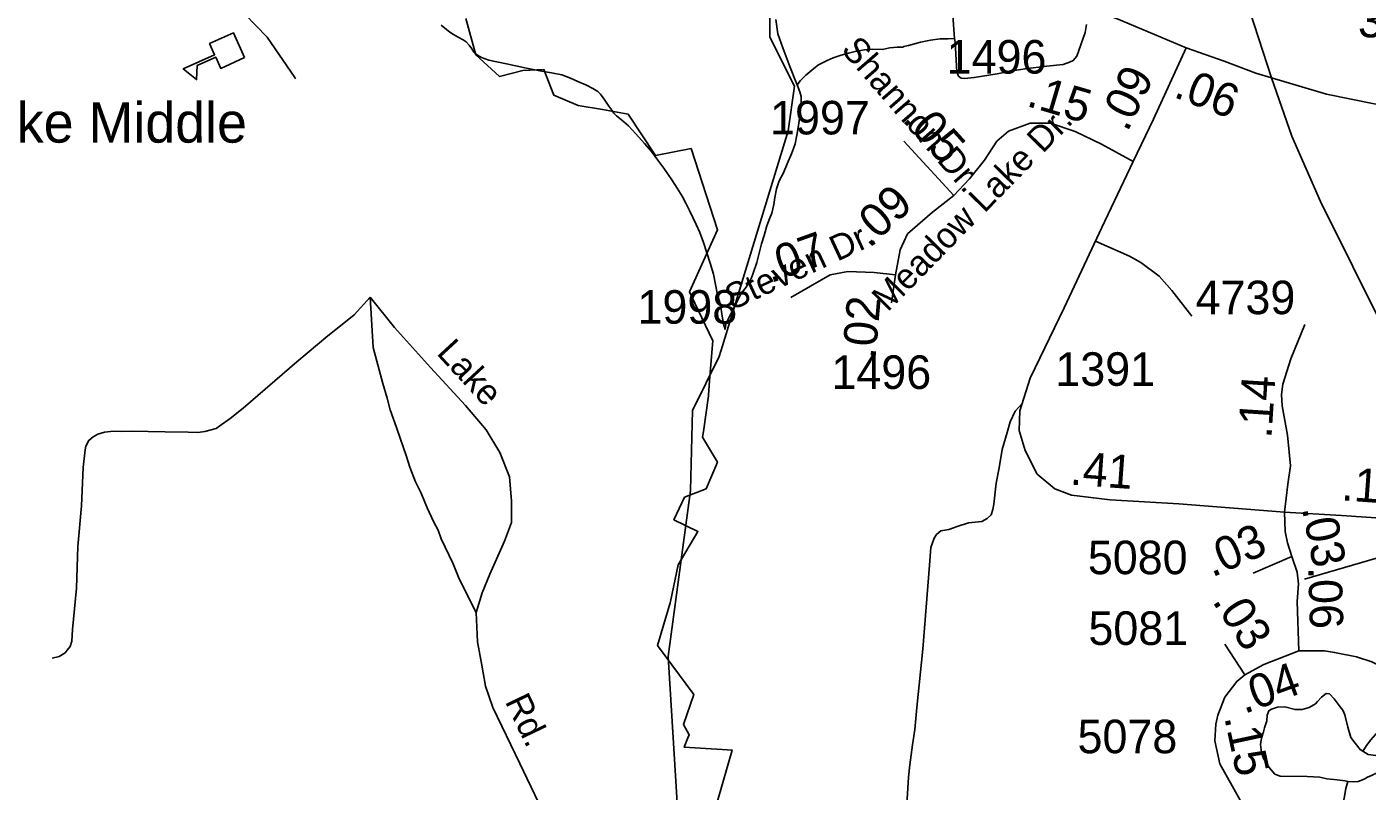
# Model space of a CAD drawing. Extents: x 2001466 to 2224147, y 644118 to 847247.
# Drawn here: x 2071075 to 2076073, y 692488 to 695337 of the extents above; entities that cross this region are included whole.
import ezdxf

# ---------------------------------------------------------------- set-up
doc = ezdxf.new("R2010")
doc.units = 0
for name, color, linetype in [('Exist Boundary Political City Limit New', 7, 'Continuous'), ('Exist Cultural Educational Facility Elementary CELL', 7, 'Continuous'), ('Exist Cultural Educational Facility High Label', 7, 'Continuous'), ('Exist Hydrographic Misc Water Feature', 7, 'Continuous'), ('Exist Road Non-System Type 51', 7, 'Continuous'), ('Exist Road Non-System Type 51 Label', 7, 'Continuous'), ('Exist Road Secondary Mileage Hundredths English Label', 7, 'Continuous'), ('Exist Road Secondary Type 51 Attributed', 7, 'Continuous'), ('Exist Road Secondary Type 51 Label', 7, 'Continuous'), ('Exist Road Secondary Type 51 Number Label', 7, 'Continuous'), ('Map Preparation Boundary City Limit Buffer Line', 7, 'Continuous')]:
    doc.layers.add(name, color=color, linetype=linetype)

msp = doc.modelspace()

# ---------------------------------------------------------------- linework, layer by layer
at = {"layer": 'Exist Boundary Political City Limit New'}
for points in [[(2073597.8, 693827.8), (2073616.8, 693960.9), (2073617.1, 693965.4), (2073622.4, 694032.9), (2073632.4, 694166.4), (2073605.2, 694223.8), (2073566.1, 694306.5), (2073546.2, 694348.6), (2073650.9, 694580.4), (2073552, 694882.9), (2073419.4, 694856.8), (2073317.4, 695010.8), (2073221.4, 695028.8), (2073131.1, 695042.9), (2073039.5, 695082.1), (2073002.2, 695177.9), (2072924.5, 695174.2), (2072837.9, 695151.9), (2072749.4, 695232.5), (2072712, 695367.1)], [(2073648.6, 692446.9), (2073704.6, 692641.3), (2073667.4, 692643.6), (2073525.8, 692652.3), (2073540.2, 692686.5), (2073545, 692697.8), (2073523.2, 692736.1), (2073562.1, 692847.8), (2073426.8, 693031.2), (2073473.8, 693189.9), (2073474.9, 693194.9), (2073503.8, 693331.6), (2073577.6, 693455.6), (2073487.8, 693499.7), (2073527.6, 693583.3), (2073608.1, 693614.9), (2073650.2, 693714.5), (2073594.9, 693807.1), (2073597.8, 693827.8)]]:
    msp.add_lwpolyline(points, dxfattribs=at)
at = {"layer": 'Exist Cultural Educational Facility Elementary CELL'}
msp.add_lwpolyline([(2071887.1, 695221.9), (2071797.9, 695181.6), (2071779, 695223.6), (2071710.5, 695192.8), (2071707.7, 695139.9), (2071657.8, 695179.6), (2071775, 695232.4), (2071756.1, 695274.3), (2071845.4, 695314.6)], close=True, dxfattribs=at)
at = {"layer": 'Exist Hydrographic Misc Water Feature'}
for points in [[(2073669.2, 694148), (2073914, 694948.9), (2073938, 695115.7), (2073845.9, 695298), (2073845.9, 695498.2), (2073986, 696249.9), (2073986, 696446.8), (2074069, 696799.4), (2074033.9, 697282.4), (2073942.1, 697556.6), (2074016.1, 698122.6), (2074223, 698630.2), (2074223, 698899.3), (2074256, 698941.2)], [(2074534.7, 695293.3), (2074524.6, 695431.1)], [(2072619.7, 695342.2), (2072639.6, 695326.2), (2072651.9, 695316.2), (2072665.8, 695308), (2072683.7, 695298.4), (2072701.7, 695288.3), (2072713.4, 695280.1), (2072723.9, 695268.4), (2072733.7, 695254.3), (2072741.5, 695242.2), (2072746, 695238.3), (2072755.7, 695230.3), (2072769.8, 695222.5), (2072797.9, 695212.5), (2072863.9, 695198.5), (2072937.7, 695182.8), (2072988, 695172.8), (2073031.7, 695164.9), (2073070, 695157.1), (2073102, 695145), (2073129.7, 695133), (2073161.9, 695119.2), (2073185.7, 695107.1), (2073203.7, 695095), (2073213.9, 695085.4), (2073224, 695071.3), (2073232.2, 695059.1), (2073245.7, 695041.2), (2073255.8, 695025.5), (2073264, 695015.3), (2073274.2, 695005.3), (2073291.9, 694989.6), (2073317.9, 694967.4), (2073346.2, 694937.6), (2073378, 694901.5), (2073404, 694871.6), (2073428.4, 694839.5), (2073450.4, 694809.9), (2073466.2, 694785.9), (2073480.3, 694765.9), (2073500.4, 694735.7), (2073518.9, 694705.8)], [(2073867.4, 695364.4), (2073875.4, 695310.4), (2073893.5, 695258.6), (2073919.7, 695188.5), (2073943.7, 695128.5), (2073947.8, 695120.6)], [(2075026.6, 695344.8), (2075020.9, 695314.9), (2074990.7, 695226.6), (2074977, 695210.4), (2074962.8, 695204.4), (2074939.1, 695196.3), (2074879, 695190.4), (2074797.4, 695180), (2074749.2, 695171.9), (2074693, 695161.8), (2074607.5, 695147.6), (2074571, 695143.4), (2074559.3, 695145.1), (2074549.2, 695153.2), (2074543.3, 695169.1), (2074537.1, 695279.1), (2074534.7, 695293.3)], [(2074534.7, 695293.3), (2074511.1, 695291.2), (2074481, 695291.3), (2074444.9, 695287), (2074406.9, 695279), (2074362.9, 695266.6), (2074345.2, 695262.8), (2074341.1, 695260.6)], [(2074341.1, 695260.6), (2074321, 695260.7), (2074293.1, 695258.5), (2074264.8, 695252.6), (2074229.2, 695252.8), (2074199.2, 695250.8), (2074163.3, 695244.9), (2074139.3, 695238.8), (2074111.3, 695230.9), (2074081.5, 695220.8), (2074059.4, 695210.7), (2074027.4, 695194.9), (2074009.3, 695180.6), (2073979.4, 695156.8), (2073959.5, 695136.7), (2073947.8, 695120.6)], [(2073947.8, 695120.6), (2073957.7, 695094.8), (2073961.8, 695076.7), (2073962, 695056.8), (2073959.9, 695026.7), (2073954, 694976.5), (2073946, 694932.7), (2073940.2, 694900.7), (2073934.1, 694882.6), (2073926.1, 694862.7), (2073910.3, 694826.5), (2073896.2, 694792.6), (2073880.2, 694762.5), (2073870.5, 694732.3), (2073864.4, 694700.5), (2073860.5, 694674.7), (2073852.5, 694642.6), (2073844.7, 694620.7), (2073834.8, 694594.6), (2073824.8, 694558.4), (2073814.8, 694528.3), (2073796.7, 694458.4), (2073782.8, 694418.3), (2073776.8, 694400.6), (2073771.1, 694388.5), (2073757.1, 694366.2), (2073739.1, 694342.2), (2073716.9, 694298.5), (2073699.3, 694264.3), (2073687.2, 694242.2), (2073681.3, 694230.1), (2073679, 694208.1)], [(2073518.9, 694705.8), (2073532.8, 694679.7), (2073546.3, 694652.1), (2073570.9, 694600.1), (2073584.5, 694570.1), (2073598.6, 694532.2), (2073611.1, 694494.2), (2073623, 694456.3), (2073635.1, 694414.4), (2073643.1, 694376.2), (2073650.9, 694338.1), (2073661.2, 694300.1), (2073667.3, 694258.2), (2073673.3, 694230.1), (2073679, 694208.1)], [(2073422.7, 691491.3), (2073427.8, 692107.8), (2073501.8, 692424.5), (2073467, 692989.6), (2073550, 693607.9), (2073557, 693906.3), (2073656.9, 694107.7), (2073669.2, 694148)], [(2076001.2, 692524.2), (2075991, 692526.6), (2075961, 692530.3), (2075922.9, 692534), (2075897.1, 692539.9), (2075873.3, 692541.9), (2075849.1, 692542), (2075749, 692543.7), (2075729.1, 692551.6), (2075707.2, 692575.7), (2075686.9, 692609.5), (2075679.1, 692631.4), (2075674.8, 692661.3), (2075678.7, 692685.4), (2075686.5, 692709.4), (2075690.6, 692723.4), (2075698.4, 692749.4), (2075700.2, 692771.4), (2075706.4, 692787.5), (2075716.2, 692793.3), (2075738.3, 692801.3), (2075766, 692801.6), (2075804.4, 692791.7), (2075830.4, 692791.8), (2075856.2, 692800), (2075880.2, 692813.8), (2075888, 692822), (2075902.2, 692838.1), (2075919.8, 692852.1), (2075932.3, 692850.2), (2075950.2, 692832.1), (2075972.3, 692802.3), (2075982.2, 692790.3), (2075990.4, 692772.5), (2076000.4, 692726.3), (2076012.5, 692688.4), (2076028.7, 692666.5), (2076046.9, 692642.6), (2076057, 692636.6)], [(2076144.6, 692748.7), (2076112.8, 692708.5), (2076086.5, 692678.8), (2076070.7, 692658.5), (2076060.9, 692642.5), (2076057, 692636.6)], [(2076057, 692636.6), (2076076.7, 692624.7), (2076104.8, 692620.8), (2076122.6, 692622.6), (2076160.8, 692627), (2076170.6, 692625.1), (2076174.9, 692607), (2076174.9, 692587.1), (2076166.9, 692576.9), (2076150.9, 692572.9), (2076115, 692558.8), (2076089.2, 692546.5), (2076074.8, 692540.6), (2076061.3, 692532.5), (2076039.2, 692524.5), (2076021.3, 692522.4), (2076001.2, 692524.2)], [(2076001.2, 692524.2), (2075993, 692498.3), (2075987.1, 692462.2), (2075983.2, 692446.2)]]:
    msp.add_lwpolyline(points, dxfattribs=at)
at = {"layer": 'Exist Road Non-System Type 51'}
for points in [[(2075060, 694537.4), (2075186.9, 694482), (2075228.7, 694458.1), (2075297.3, 694407.4), (2075345, 694353.8), (2075419.5, 694258.3)], [(2071168.9, 692984.1), (2071195, 692989.6), (2071217.3, 693003.1), (2071225.5, 693013), (2071235.8, 693026.8), (2071242.2, 693046.6), (2071245.1, 693090.6), (2071260.2, 693244.3), (2071265.4, 693400.2), (2071278.5, 693551.9), (2071285.4, 693693.8), (2071292.7, 693759.6), (2071295, 693773.6), (2071305.5, 693795.4), (2071321.7, 693809), (2071339.9, 693818.7), (2071352, 693822.4), (2071364.1, 693826.2), (2071398.2, 693829.5), (2071426.1, 693828.9), (2071464.2, 693830.1), (2071590.1, 693827.6), (2071676.1, 693825.8), (2071712.1, 693825.1), (2071738.1, 693828.6), (2071780.4, 693839.7), (2071794.6, 693849.4), (2071833.1, 693876.6), (2071881.9, 693915.6), (2072081.4, 694087.6), (2072197.4, 694185.2), (2072256.4, 694232), (2072295, 694263.2), (2072354.8, 694328.6)], [(2072354.8, 694328.6), (2072445.6, 694215.9), (2072580.1, 694066.9), (2072710.9, 693925.1), (2072787.2, 693834.2), (2072838.1, 693750.6), (2072874.4, 693659.7), (2072881.7, 693568.8), (2072881.7, 693488.8), (2072856.3, 693419.7), (2072801.8, 693296.1), (2072772.7, 693227), (2072750, 693153.3)], [(2072354.8, 694328.6), (2072366.5, 694141.8), (2072401.8, 694007), (2072418.7, 693952.7), (2072429.8, 693908.5), (2072441.2, 693878.2), (2072454.4, 693840), (2072490.2, 693735.2), (2072503.4, 693695), (2072524.3, 693640.5), (2072545.5, 693598.1), (2072568.3, 693543.6), (2072591.3, 693493.2), (2072608.6, 693460.8), (2072620, 693428.6), (2072664.1, 693335.7), (2072685.1, 693285.2), (2072719.6, 693214.5), (2072750, 693153.3)], [(2074787.4, 693934), (2074760.5, 693904.2), (2074741.7, 693864.5), (2074730.9, 693824.8), (2074711.6, 693761.2), (2074700.2, 693693.4), (2074689, 693635.6), (2074681.4, 693557.8), (2074677, 693537.9), (2074670.6, 693518), (2074656.3, 693504.3), (2074636.1, 693492.7), (2074586, 693487.7), (2074543.7, 693474.6), (2074513.5, 693463.2), (2074483.4, 693457.8), (2074467.1, 693444.2), (2074458.8, 693430.3), (2074446.1, 693396.6), (2074440.8, 693330.7), (2074416.4, 693017.2), (2074393.9, 692799.7), (2074386.2, 692717.8), (2074377.1, 692660), (2074367.6, 692586.2), (2074362.6, 692540.3), (2074337.2, 692129.1)], [(2072750, 693153.3), (2072755.4, 693044.4), (2072771.8, 692957.1), (2072785.4, 692879.8), (2072812.7, 692799.9), (2072912.9, 692590.6), (2072997.1, 692417.2)]]:
    msp.add_lwpolyline(points, dxfattribs=at)
at = {"layer": 'Exist Road Secondary Type 51 Attributed'}
for points in [[(2071451.7, 696282.8), (2071437.7, 696132.2), (2071436.1, 696032.7), (2071453.5, 695941.2), (2071480.3, 695866.9), (2071521.3, 695765.9), (2071603, 695641.9), (2071699.3, 695543.2), (2071846, 695427.2), (2071970.7, 695297.7), (2072074.8, 695147.7), (2072077.3, 695143.2)], [(2075397.9, 695258.1), (2075138, 695367), (2075004.2, 695411.2), (2074843.3, 695450.7), (2074551.4, 695517), (2074419.6, 695552.6), (2074139.1, 695675.7), (2073881.9, 695797.3), (2073706.7, 695866.8), (2073393.5, 695945), (2073011.2, 696036.6), (2072575.7, 696150.2), (2072284.6, 696215), (2072003.7, 696246.6), (2071613.9, 696278.9), (2071451.7, 696282.8)], [(2075547, 695807.7), (2075561.3, 695650), (2075602.7, 695495.6), (2075716.7, 695146.7)], [(2075200.1, 694834.2), (2075276.6, 694992.9), (2075397.9, 695258.1)], [(2075716.7, 695146.7), (2075658.3, 695163.3), (2075540, 695208.3), (2075397.9, 695258.1)], [(2076804.7, 694994.4), (2076510, 695003.8), (2076269, 695021.2), (2076098.6, 695049.6), (2075921.8, 695085.9), (2075716.7, 695146.7)], [(2075716.7, 695146.7), (2075792.6, 694929), (2075899.2, 694685.8), (2076139.8, 694201), (2076322.9, 693806.2), (2076466.5, 693492)], [(2075200.1, 694834.2), (2075082.1, 694899), (2074984.3, 694946.4), (2074892.8, 694977.9), (2074817, 694977.9), (2074735, 694947.9), (2074692.4, 694910), (2074646.6, 694839), (2074589.8, 694769.5), (2074531.4, 694707.9)], [(2074531.4, 694707.9), (2074345.6, 694910.8)], [(2075764.8, 693527.4), (2075370.5, 693558.3), (2075114.9, 693574.1), (2074970.9, 693591.5), (2074908.6, 693614.4), (2074843.1, 693669.6), (2074797.3, 693757.3), (2074775.2, 693832.3), (2074778.4, 693904.9), (2074816.2, 694026.5), (2074943.7, 694289.5), (2075084.1, 694588.7), (2075200.1, 694834.2)], [(2074531.4, 694707.9), (2074452.5, 694646.3), (2074359, 694565), (2074332.2, 694505.8), (2074314, 694412.6)], [(2074314, 694412.6), (2074234.4, 694421.3), (2074136.5, 694424.5), (2074070.2, 694411.8), (2073923.5, 694328.1)], [(2074314, 694412.6), (2074299.5, 694308)], [(2075764.8, 693527.4), (2075777.2, 693632.4), (2075786.8, 693699.9), (2075775.6, 693815.2), (2075756, 693924.2), (2075753.8, 693965.7), (2075758.1, 694004.9), (2075788.7, 694098.6), (2075841, 694227.3)], [(2076466.5, 693492), (2076289.7, 693493.6), (2075977.3, 693515.7), (2075764.8, 693527.4)], [(2075792.7, 693362.7), (2075775.9, 693413), (2075767.7, 693455.5), (2075764.8, 693527.4)], [(2075792.7, 693362.7), (2075648.3, 693300)], [(2075817.8, 693010.6), (2075812.2, 693195), (2075817.2, 693261), (2075812.2, 693304), (2075792.7, 693362.7)], [(2075616.5, 692921.5), (2075542.2, 693035.6)], [(2075817.8, 693010.6), (2075687.4, 692959.9), (2075616.5, 692921.5)], [(2076837.5, 692743.8), (2076795.3, 692728.3), (2076736.7, 692711.5), (2076718.1, 692709.4), (2076699.3, 692708.5), (2076669.6, 692711.5), (2076580.3, 692739.5), (2076513.2, 692759), (2076463, 692767.4), (2076395.9, 692778.6), (2076330.2, 692797), (2076287, 692826.1), (2076211.6, 692887.6), (2076133.4, 692949.1), (2076090.3, 692970.5), (2076032.9, 692988.2), (2075951.9, 693005), (2075913.6, 693010.3), (2075817.8, 693010.6)], [(2075616.5, 692921.5), (2075586.9, 692897), (2075542.5, 692838.6), (2075516.1, 692771.5), (2075509, 692738.1), (2075505, 692675.2), (2075523.5, 692589.2), (2075569.6, 692507.6), (2075605.2, 692442.7), (2075621.9, 692396.7), (2075636.6, 692350.7), (2075636.6, 692300.4), (2075632.4, 692229.3), (2075630.3, 692206.3)]]:
    msp.add_lwpolyline(points, dxfattribs=at)
at = {"layer": 'Exist Road Secondary Type 51 Number Label'}
msp.add_lwpolyline([(2075839.7, 693278.1), (2076683.1, 693524.3), (2077034.1, 693801.9)], dxfattribs=at)
at = {"layer": 'Map Preparation Boundary City Limit Buffer Line'}
for points in [[(2073597.8, 693827.8), (2073616.8, 693960.9), (2073617.1, 693965.4), (2073622.4, 694032.9), (2073632.4, 694166.4), (2073605.2, 694223.8), (2073566.1, 694306.5), (2073546.2, 694348.6), (2073650.9, 694580.4), (2073552, 694882.9), (2073419.4, 694856.8), (2073317.4, 695010.8), (2073221.4, 695028.8), (2073131.1, 695042.9), (2073039.5, 695082.1), (2073002.2, 695177.9), (2072924.5, 695174.2), (2072837.9, 695151.9), (2072749.4, 695232.5), (2072712, 695367.1)], [(2073648.6, 692446.9), (2073704.6, 692641.3), (2073667.4, 692643.6), (2073525.8, 692652.3), (2073540.2, 692686.5), (2073545, 692697.8), (2073523.2, 692736.1), (2073562.1, 692847.8), (2073426.8, 693031.2), (2073473.8, 693189.9), (2073474.9, 693194.9), (2073503.8, 693331.6), (2073577.6, 693455.6), (2073487.8, 693499.7), (2073527.6, 693583.3), (2073608.1, 693614.9), (2073650.2, 693714.5), (2073594.9, 693807.1), (2073597.8, 693827.8)]]:
    msp.add_lwpolyline(points, dxfattribs=at)

# ---------------------------------------------------------------- texts
at = {"layer": 'Exist Cultural Educational Facility High Label'}
msp.add_text('West Lake Middle', height=150, dxfattribs=at).set_placement((2070301.6, 694904.9))
at = {"layer": 'Exist Road Non-System Type 51 Label'}
for s, rotation, p in [('Lake', 312.6979, (2072599.5, 694118.4)), ('Rd.', 295.5886, (2072856.3, 692822.6))]:
    msp.add_text(s, height=95, rotation=rotation, dxfattribs=at).set_placement(p)
at = {"layer": 'Exist Road Secondary Mileage Hundredths English Label'}
for s, rotation, p in [('.09', 63.9657, (2075178.6, 694941.2)), ('.06', 338.905, (2075347, 695076.2)), ('.15', 343.4806, (2074798.6, 695042.4)), ('.05', 312.2217, (2074335.9, 694989.1)), ('.09', 43.0663, (2074215.9, 694508.7)), ('.07', 19.689, (2073848.2, 694380.3)), ('.02', 85.0997, (2074239.4, 694095.6)), ('.14', 86.2846, (2075715.9, 693801.1)), ('.41', 355.8847, (2074962.9, 693630.5)), ('.14', 355.8847, (2075974.8, 693572.1)), ('.03', 280.9536, (2075829.4, 693543)), ('.03', 23.4612, (2075494.6, 693283.6)), ('.06', 271.7346, (2075853, 693323)), ('.03', 303.0605, (2075493.3, 693195.9)), ('.04', 19.9741, (2075614.8, 692775.1)), ('.15', 282.1231, (2075539.8, 692763))]:
    msp.add_text(s, height=125, rotation=rotation, dxfattribs=at).set_placement(p)
at = {"layer": 'Exist Road Secondary Type 51 Label'}
for s, rotation, p in [('Shannon Dr.', 311.0433, (2074107.8, 695248.9)), ('Meadow Lake Dr.', 45.628, (2074285.2, 694271.2)), ('Steven Dr.', 24.9466, (2073706.2, 694279.1))]:
    msp.add_text(s, height=95, rotation=rotation, dxfattribs=at).set_placement(p)
at = {"layer": 'Exist Road Secondary Type 51 Number Label'}
for s, p in [('3943', (2076038.8, 695297.3)), ('1496', (2074505.1, 695162.2)), ('1997', (2073846.5, 694935.5)), ('4739', (2075433.2, 694265.5)), ('1998', (2073352.1, 694230.1)), ('1496', (2074075.4, 693987)), ('1391', (2074910.3, 693998.5)), ('5080', (2075031.5, 693296.5)), ('5081', (2075033.7, 693032.9)), ('5078', (2074993.1, 692629.2))]:
    msp.add_text(s, height=125, dxfattribs=at).set_placement(p)

doc.saveas('drawing.dxf')
